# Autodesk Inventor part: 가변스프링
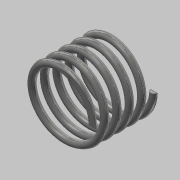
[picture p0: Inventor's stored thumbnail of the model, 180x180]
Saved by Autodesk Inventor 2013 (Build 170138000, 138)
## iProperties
Created: 2019-01
Part Number: 가변스프링
Material: 스테인리스강
Document SubType Name: Modeling
Designer: Gpr
Density: 8.08 g/cm^3
Mass: 7.79367 g
Surface Area: 19.6283 cm^2
Volume: 0.964563 cm^3
Author: Gpr
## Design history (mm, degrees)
sketch "스케치1"
  geometry: L1 (0, 0)-(10, 0); L2 (10, 0)-(10, 18.7); L3 (10, 18.7)-(0, 18.7); L4 (0, 18.7)-(0, 0); C1 r 1 at (10, 0)
  constraints: 8 end point, 2 parallel, 1 centre point, 1 coincident, 1 horizontal, 1 perpendicular
  dimensions: "d0" = 18.7 distance of L1.end L2.end (derived); "d2" = 2 diameter of C1; "d3" = 20 diameter of L2 L4
feature "코일1" sketch "스케치1" pitch "d4" = 10; turns "d6" = 5; dims "d5" = 18.7 (= d0), "d7" = 0, angle "d8" = 90 deg, angle "d9" = 90 deg, "d10" = 0, "d11" = 0
sketch "스케치2"
  geometry: L1 (0, 12.5)-(18.7, 12.5); L2 (18.7, 12.5)-(18.7, -12.5); L3 (18.7, -12.5)-(0, -12.5); L4 (0, -12.5)-(0, 12.5); 2 further points
  constraints: 8 end point, 2 parallel, 1 coincident, 1 horizontal, 1 midpoint, 1 perpendicular
  dimensions: "d12" = 18.7 distance of L2.end L3.end (derived); "d14" = 25 distance of L3.end L1.start
extrude "돌출1" sketch "스케치2" stored distance "d15" = 25; taper "d16" = 0 deg
node "솔리드1"
